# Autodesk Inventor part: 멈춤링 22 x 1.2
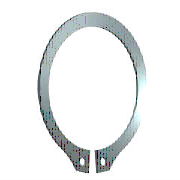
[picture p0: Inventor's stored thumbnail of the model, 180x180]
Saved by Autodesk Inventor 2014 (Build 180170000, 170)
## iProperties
IsCustomPart: 0
Created: 2009-02
Part Number: 멈춤링 22 x 1.2
Material: Steel, Mild
Description: 리테이닝 링(C형)
Document SubType Name: Modeling
Standard: KS B 1336
Designer: SeoGD™
Standards Organization: KS
Language: ko-KR
Size Designation: 22 x 1.2
Categories: <MemberInstance><Categories><Category DisplayName="샤프트 부품" InternalName="7f7aeb1f-a693-4053-b835-cee3144e0d98" Mnemonic="SHFT"><Category DisplayName="써클립" Inter
Density: 1 g/cm^3
Appearance: Metal-Steel
Author: SeoGD™
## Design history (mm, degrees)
sketch "스케치1"
  geometry: L1 (-6, 0)-(6, 0) reference; L2 (0, 20.189)-(0, -80.536) reference; L3 (-48.09, 0)-(48.09, 0) reference; L4 (-0.5, -21.488)-(-0.5, -25.588); L5 (-0.5, -6.54)-(-0.5, -13.29); L6 (-2.795, 2.7)-(3.672, 2.7); L7 (0.5, -6.54)-(0.5, -13.29); L8 (0.5, -21.488)-(0.5, -25.588); C1 r 1 at (-2, -23.437); C2 r 1 at (2, -23.437); A1 r 10.5 centre (0, -11) between (0.5, -21.488) and (-0.5, -21.488); A2 r 13.025 centre (0, -10.325) between (5.149, -22.289) and (-5.149, -22.289); A3 r 14.597 centre (0, -11) between (-2.318, -25.411) and (-0.5, -25.588); A4 r 2 centre (-2, -23.437) between (-3.97, -23.781) and (-2.318, -25.411); A5 r 2 centre (-5.94, -24.126) between (-3.97, -23.781) and (-5.149, -22.289); A6 r 2 centre (5.94, -24.126) between (5.149, -22.289) and (3.97, -23.781); A7 r 2 centre (2, -23.437) between (2.318, -25.411) and (3.97, -23.781); A8 r 14.597 centre (0, -11) between (0.5, -25.588) and (2.318, -25.411)
  constraints: 16 point on circle, 12 end point, 10 centre point, 9 symmetric about line, 5 point on line, 4 tangent, 3 coincident, 2 horizontal, 1 perpendicular, 1 vertical, 5 other
  dimensions: "d0" = 21 diameter of A1 (= ND); "d1" = 4.1 distance of L4.end L4.start (= SRB2); "d6" = 0.5 distance between parallel lines of L2 L5 (= 0.25 x SD5); "d7" = 2.7 distance between parallel lines of L6 L3 (= SRB1); "d8" = 0.675 distance of A1.centre A2.centre (= 0.25 x SRB1); "d9" = 2 radius of A4 (= SD5); "d10" = 2 radius of A5 (= SD5); "d11" = 1.5 distance from line of L4 A4.centre (= 0.75 x SD5); "d12" = 2 diameter of C1 (= SD5); "d13" = 2 diameter of C2 (= SD5); "d14" = 11 distance from line of A1.centre L1 (= 0.5 x WD)
extrude "본체" new body sketch "스케치1" distance "d2" = 1.2 (= SD); taper "d3" = 0 deg
workaxis "Work Axis1"
workplane "Work Plane1"
body "Solid1"
other parameters: "WD" = 22 (= WDMIN) [user parameter; used in 1 equation term], "SD" = 1.2 [user parameter; used in 1 equation term], "SRB1" = 2.7 [user parameter; used in 2 equation terms], "ND" = 21 [user parameter; used in 1 equation term], "SRB2" = 4.1 [user parameter; used in 1 equation term], "SD5" = 2 [user parameter; used in 6 equation terms], "d15" = 0, "d16" = 0, "d17" = 0, "d41" = 0, "d42" = 0, "WDMIN" = 22 [user parameter; used in 1 equation term], "SD3" = 20.5 [user parameter], "WDMAX" = 24 [user parameter]
